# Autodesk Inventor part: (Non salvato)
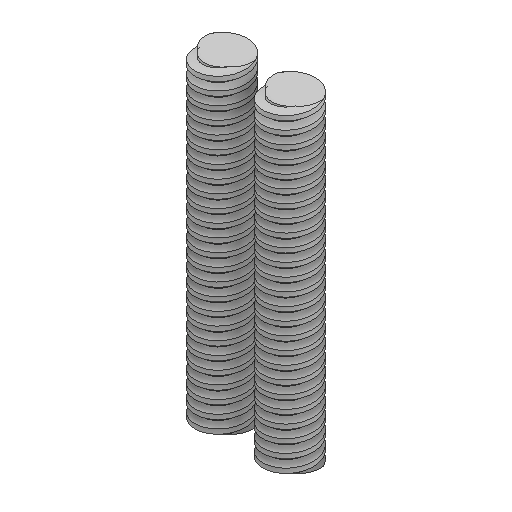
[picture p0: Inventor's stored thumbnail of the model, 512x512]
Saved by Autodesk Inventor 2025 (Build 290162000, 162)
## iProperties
Created: 2024-10
Part Number: (Non salvato)
Material: Acciaio
Document SubType Name: Modeling
Designer: R5800u
Density: 7.85 g/cm^3
Appearance: Default
Title: T12.step
Sending System: Autodesk Translation Framework v13.20.0.188
Preprocessor: ST-DEVELOPER v20
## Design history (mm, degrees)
feature "Corpo1"
feature "Corpo2"
node "Solido1"
node "Solido2"
